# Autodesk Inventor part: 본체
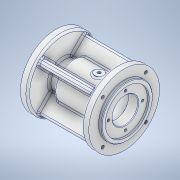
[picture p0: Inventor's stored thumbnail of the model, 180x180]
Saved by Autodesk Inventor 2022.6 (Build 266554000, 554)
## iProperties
Created: 2024-10
Part Number: 본체
Material: 알루미늄 6061
Document SubType Name: Modeling
Designer: Class 001
Density: 2.7 g/cm^3
Appearance: 알루미늄 - 평지
Mass: 1166 g
Surface Area: 968.822 cm^2
Volume: 431.851 cm^3
Author: Class 001
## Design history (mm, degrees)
sketch "스케치3"
  geometry: L1 (0, 0)-(15, 0); L2 (15, 0)-(15, 23); L3 (15, 23)-(0, 23); L4 (0, 23)-(0, 0); L5 (15, 0)-(88, 0); L6 (88, 0)-(88, 30); L7 (88, 30)-(15, 30); L8 (15, 30)-(15, 0); 1 further point
  constraints: 16 end point, 4 parallel, 2 horizontal, 2 perpendicular
  dimensions: "d7" = 46 diameter of L3 L1; "d8" = 15 distance of L2.end L3.end; "d9" = 73 distance of L6.end L7.end; "d10" = 60 diameter of L7 L5
revolve "회전1" sketch "스케치3" stored, may be unused: angle "d11" = 90 deg
sketch "스케치4"
  geometry: C1 r 58 at (0, 0); 1 further point
  constraints: 1 centre point, 1 coincident
  dimensions: "d12" = 116 diameter of C1
extrude "돌출1" join sketch "스케치4" distance "d13" = 12; taper "d14" = 0 deg
sketch "스케치5"
  geometry: C1 r 42 at (0, 0); 1 further point
  constraints: 1 centre point, 1 coincident
  dimensions: "d15" = 84 diameter of C1
extrude "돌출2" join sketch "스케치5" distance "d16" = 5; taper "d17" = 0 deg
sketch "스케치6"
  geometry: C1 r 58 at (0, 0); 1 further point
  constraints: 1 centre point, 1 coincident
  dimensions: "d18" = 116 diameter of C1
extrude "돌출3" join sketch "스케치6" distance "d19" = 12; taper "d20" = 0 deg
sketch "스케치7"
  geometry: C1 r 42 at (0, 0); 1 further point
  constraints: 1 centre point, 1 coincident
  dimensions: "d21" = 84 diameter of C1
extrude "돌출4" join sketch "스케치7" distance "d22" = 5; taper "d23" = 0 deg
sketch "스케치8"
  geometry: L1 (105, -42)-(105, 42) reference; L2 (105, 36)-(102, 36); L3 (102, 36)-(102, 0); L4 (102, 0)-(105, 0); L5 (105, 0)-(105, 36); L6 (102, 0)-(86, 0); L7 (86, 0)-(86, 21); L8 (86, 21)-(102, 21); L9 (102, 21)-(102, 0); L10 (86, 0)-(32, 0); L11 (32, 0)-(32, 25); L12 (32, 25)-(86, 25); L13 (86, 25)-(86, 0); L14 (32, 0)-(20, 0); L15 (20, 0)-(20, 21); L16 (20, 21)-(32, 21); L17 (32, 21)-(32, 0); L18 (20, 0)-(2, 0); L19 (2, 0)-(2, 18); L20 (2, 18)-(20, 18); L21 (20, 18)-(20, 0); L22 (2, 0)-(-2, 0); L23 (-2, 0)-(-2, 16); L24 (-2, 16)-(2, 16); L25 (2, 16)-(2, 0); L26 (-2, 0)-(-5, 0); L27 (-5, 0)-(-5, 10.5); L28 (-5, 10.5)-(-2, 10.5); L29 (-2, 10.5)-(-2, 0); 8 further points
  constraints: 56 end point, 14 parallel, 7 horizontal, 7 perpendicular, 1 horizontal alignment, 1 point on line
  dimensions: "d24" = 72 diameter of L2 L4; "d25" = 3 distance of L2.start L2.end; "d26" = 42 diameter of L8 L6; "d27" = 16 distance of L7.end L8.end; "d28" = 54 distance of L11.end L12.end; "d29" = 50 diameter of L12 L10; "d30" = 12 distance of L15.end L16.end; "d31" = 42 diameter of L16 L14; "d32" = 18 distance of L19.end L20.end; "d33" = 36 diameter of L20 L18; "d34" = 4 distance of L23.end L24.end; "d35" = 32 diameter of L24 L22; "d36" = 3 distance of L27.end L28.end; "d37" = 21 diameter of L28 L26
revolve "회전2" stored, may be unused: angle "d38" = 90 deg
revolve "회전3" stored, may be unused: angle "d39" = 90 deg
fillet "모깎기1" dims "d40" = 3
fillet "모깎기2" dims "d41" = 0.6
chamfer "모따기1" distance "d42" = 1; stored, may be unused: second distance "d43" = 2, angle "d44" = 30 deg
fillet "모깎기3" dims "d45" = 0.6
fillet "모깎기4" dims "d46" = 3
chamfer "모따기2" distance "d47" = 1; stored, may be unused: second distance "d48" = 2, angle "d49" = 30 deg
chamfer "모따기3" distance "d50" = 1; stored, may be unused: second distance "d51" = 2, angle "d52" = 30 deg
sketch "스케치9"
  geometry: C1 r 36 at (0, 0); 1 further point
  constraints: 1 centre point, 1 coincident
  dimensions: "d53" = 72 diameter of C1
extrude "돌출5" cut sketch "스케치9" distance "d54" = 4; taper "d55" = 0 deg
fillet "모깎기5" dims "d56" = 3
fillet "모깎기6" dims "d57" = 3
sketch "스케치10"
  geometry: 2 further points
  constraints: 1 horizontal alignment
  dimensions: "d58" = 28 distance of point (0, 0) point (28, 0)
hole "구멍1" sketch "스케치10" at (28, 0) diameter "d59" = 4.134; stored, may be unused: countersink angle "d63" = 82 deg, drill point angle "d65" = 118 deg; dims "d60" = 10, "d61" = 11, "d62" = 2.6, "d64" = 12
node "작업 평면4"
sketch "스케치12"
  geometry: L1 (-105, -41)-(-105, 41) reference; C1 r 7.5 at (-59, 0); 2 further points
  constraints: 1 centre point, 1 horizontal alignment, 1 midpoint
  dimensions: "d74" = 15 diameter of C1; "d75" = 46 distance from line of L1 C1.centre
extrude "돌출6" join sketch "스케치12" stored distance "d76" = 4; taper "d77" = 0 deg
sketch "스케치13"
  geometry: C1 r 7.5 at (0, 0) reference; 2 further points
  constraints: 1 coincident
hole "구멍2" sketch "스케치13" at (0, 0) diameter "d78" = 5.1881; stored, may be unused: countersink angle "d82" = 90 deg, drill point angle "d84" = 118 deg; dims "d79" = 12, "d80" = 4, "d81" = 2, "d83" = 16
fillet "모깎기7" dims "d85" = 3
sketch "스케치14"
  geometry: C1 r 58 at (0, 0) reference; A1 r 50 centre (0, 0) between (35.355, -35.355) and (0, -50); 5 further points
  constraints: 6 point on circle, 2 vertical alignment, 1 centre point, 1 coincident
  dimensions: "d87" = 100 diameter of A1; "d88" = 45 deg dimension on point (0, 0) A1.end A1.start; "d89" = 90 deg dimension on point (0, 0) point (-35.355, -35.355) A1.start; "d90" = 45 deg dimension on point (0, 0) point (35.355, 35.355) point (0, 50); "d91" = 90 deg dimension on point (0, 0) point (-35.355, 35.355) point (35.355, 35.355)
hole "구멍3" sketch "스케치14" at (-35.355, 35.355), (35.355, 35.355), (35.355, -35.355), (-35.355, -35.355) diameter "d92" = 5.1881; stored, may be unused: countersink angle "d96" = 90 deg, drill point angle "d98" = 118 deg; dims "d93" = 12, "d94" = 4, "d95" = 2, "d97" = 14
sketch "스케치15"
  geometry: C1 r 58 at (0, 0) reference; C2 r 22 at (0, 0) reference; A1 r 50 centre (0, 0) between (0, 50) and (0, -50); 5 further points
  constraints: 6 point on circle, 2 vertical alignment, 1 centre point, 1 coincident
  dimensions: "d99" = 100 diameter of A1; "d100" = 45 deg dimension on point (0, 0) A1.end point (-35.355, -35.355); "d101" = 90 deg dimension on point (0, 0) point (35.355, -35.355) point (-35.355, -35.355); "d102" = 45 deg dimension on point (0, 0) A1.start point (-35.355, 35.355); "d103" = 90 deg dimension on point (0, 0) point (35.355, 35.355) point (-35.355, 35.355)
hole "구멍4" sketch "스케치15" at (-35.355, 35.355), (35.355, 35.355), (-35.355, -35.355), (35.355, -35.355) diameter "d104" = 5.1881; stored, may be unused: countersink angle "d108" = 90 deg, drill point angle "d110" = 118 deg; dims "d105" = 12, "d106" = 4, "d107" = 2, "d109" = 14
sketch "스케치28"
  geometry: L1 (0, 0)-(-38.184, 38.184); L2 (0, 0)-(-29.81, 0)
  constraints: 4 end point, 1 horizontal
  dimensions: "d130" = 54 distance of L1.start L1.end; "d131" = 45 deg angle of L1 L2
node "작업 평면9"
sketch "스케치29"
  geometry: L1 (0, 0)-(54, 0) reference; L2 (54, 0)-(54, 88); L3 (55, 88)-(-55, 88) reference; L4 (54, 88)-(0, 88); L5 (54, 0)-(0, 0); 1 further point
  constraints: 6 end point, 1 horizontal, 1 midpoint, 1 point on line, 1 vertical
feature "리브2" sketch "스케치29" dims "d133" = 1, "d134" = 10, "d135" = 0, "d136" = 0, "d137" = 1, "d138" = 1
sketch "스케치30"
  geometry: L1 (105, -42)-(105, 42); L2 (105, 36)-(102, 36); L3 (102, 36)-(102, 0); L4 (102, 0)-(105, 0); L5 (105, 0)-(105, 36); L6 (102, 0)-(86, 0); L7 (86, 0)-(86, 21); L8 (86, 21)-(102, 21); L9 (102, 21)-(102, 0); L10 (86, 0)-(32, 0); L11 (32, 0)-(32, 25); L12 (32, 25)-(86, 25); L13 (86, 25)-(86, 0); L14 (32, 0)-(20, 0); L15 (20, 0)-(20, 21); L16 (20, 21)-(32, 21); L17 (32, 21)-(32, 0); L18 (20, 0)-(2, 0); L19 (2, 0)-(2, 18); L20 (2, 18)-(20, 18); L21 (20, 18)-(20, 0); L22 (2, 0)-(-2, 0); L23 (-2, 0)-(-2, 16); L24 (-2, 16)-(2, 16); L25 (2, 16)-(2, 0); L26 (-2, 0)-(-5, 0); L27 (-5, 0)-(-5, 10.5); L28 (-5, 10.5)-(-2, 10.5); L29 (-2, 10.5)-(-2, 0); 15 further points
  constraints: 58 end point, 14 parallel, 7 horizontal, 7 perpendicular, 1 horizontal alignment, 1 point on line
  dimensions: "d139" = 72 diameter of L2 L4; "d140" = 3 distance of L2.start L2.end; "d141" = 42 diameter of L8 L6; "d142" = 16 distance of L7.end L8.end; "d143" = 54 distance of L11.end L12.end; "d144" = 50 diameter of L12 L10; "d145" = 12 distance of L15.end L16.end; "d146" = 42 diameter of L16 L14; "d147" = 18 distance of L19.end L20.end; "d148" = 36 diameter of L20 L18; "d149" = 4 distance of L23.end L24.end; "d150" = 32 diameter of L24 L22; "d151" = 3 distance of L27.end L28.end; "d152" = 21 diameter of L28 L26
revolve "회전4" sketch "스케치30" stored, may be unused: angle "d153" = 90 deg
fillet "모깎기8" dims "d154" = 3
chamfer "모따기4" distance "d155" = 1; stored, may be unused: second distance "d156" = 2, angle "d157" = 45 deg
fillet "모깎기9" dims "d158" = 0.6
fillet "모깎기10" dims "d159" = 0.6
fillet "모깎기11" dims "d160" = 3
fillet "모깎기12" dims "d164" = 3
fillet "모깎기13" dims "d165" = 3
fillet "모깎기14" dims "d166" = 3
fillet "모깎기15" dims "d167" = 3
node "솔리드1"
pattern_circular "원형 패턴1" dims angle "d67" = 360 deg
mirror "미러1"
pattern_circular "원형 패턴2" dims angle "d162" = 360 deg
feature "A9D066F2-1C7D-4E18-AEED-F7BC21143FA4" dims "d92" = 5.1881, "d93" = 12, "d94" = 4, "d95" = 2, "d96" = 90 deg, "d97" = 14, "d98" = 118 deg
other parameters: "d73" = 32, "d132" = 90 deg
